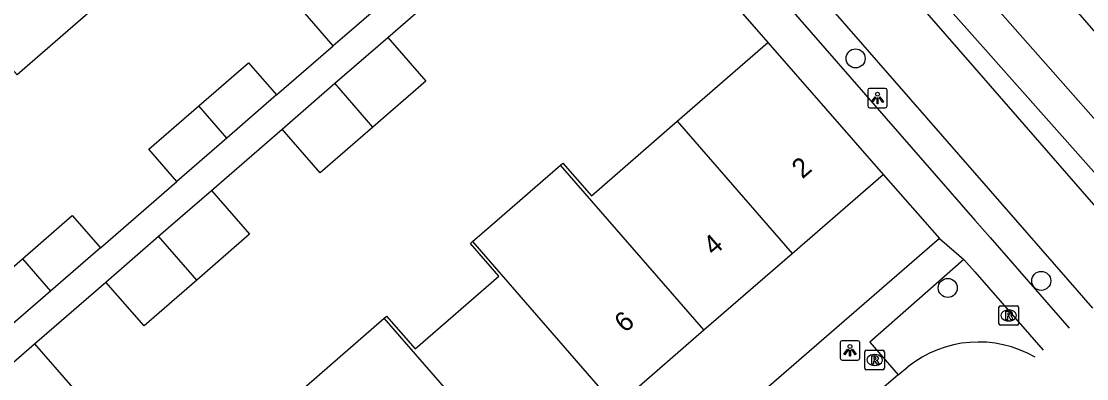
# Model space of a CAD drawing. Extents: x 155888 to 156864, y 383882 to 384671.
# Drawn here: x 156451 to 156505.7, y 384036.4 to 384054.8 of the extents above; entities that cross this region are included whole.
import ezdxf

# ---------------------------------------------------------------- set-up
doc = ezdxf.new("R2010")
doc.units = 0
for name, color, linetype in [('IMGEO_Boom', 7, 'Continuous'), ('IMGEO_Fietspad_gesloten', 7, 'Continuous'), ('IMGEO_Greppel_droge_sloot', 7, 'Continuous'), ('IMGEO_Lichtpunt', 7, 'Continuous'), ('IMGEO_Muur', 7, 'Continuous'), ('IMGEO_OVBaan_gesloten', 7, 'Continuous'), ('IMGEO_Pand', 7, 'Continuous'), ('IMGEO_Pand_nummerreeks', 7, 'Continuous'), ('IMGEO_Rijbaan_lokaal_gesloten', 7, 'Continuous'), ('IMGEO_Rioolput', 7, 'Continuous'), ('IMGEO_Voetpad_open', 7, 'Continuous')]:
    doc.layers.add(name, color=color, linetype=linetype)

msp = doc.modelspace()

# ---------------------------------------------------------------- linework, layer by layer
at = {"layer": 'IMGEO_Boom'}
for centre in [(156493.878, 384052.911), (156503.413, 384041.47), (156498.61, 384041.107)]:
    msp.add_circle(centre, 0.489, dxfattribs=at)
at = {"layer": 'IMGEO_Fietspad_gesloten'}
for points in [[(156508.758, 384042.359), (156507.724, 384043.553), (156500, 384052.421), (156466.101, 384091.342), (156424.652, 384138.668), (156398.32, 384169.108)], [(156506.058, 384040.061), (156504.79, 384041.525), (156500, 384047.025), (156463.606, 384088.814)]]:
    msp.add_lwpolyline(points, dxfattribs=at)
at = {"layer": 'IMGEO_Greppel_droge_sloot'}
msp.add_lwpolyline([(156509.636, 384043.106), (156500, 384053.967), (156494.009, 384060.719), (156471.994, 384086.237), (156471.129, 384087.831), (156471.811, 384088.508), (156473.933, 384086.903), (156495.233, 384062.187), (156500, 384056.78), (156511.018, 384044.283)], dxfattribs=at)
at = {"layer": 'IMGEO_Lichtpunt'}
for p, q in [((156494.502, 384051.273), (156494.502, 384050.466)), ((156494.502, 384051.273), (156494.502, 384050.466)), ((156495.404, 384051.368), (156494.596, 384051.368)), ((156495.404, 384051.368), (156494.596, 384051.368)), ((156495.498, 384050.466), (156495.498, 384051.273)), ((156495.498, 384050.466), (156495.498, 384051.273)), ((156494.596, 384050.372), (156495.404, 384050.372)), ((156494.596, 384050.372), (156495.404, 384050.372)), ((156493.092, 384038.297), (156493.092, 384037.49)), ((156493.092, 384038.297), (156493.092, 384037.49)), ((156493.994, 384038.392), (156493.186, 384038.392)), ((156493.994, 384038.392), (156493.186, 384038.392)), ((156494.088, 384037.49), (156494.088, 384038.297)), ((156494.088, 384037.49), (156494.088, 384038.297)), ((156493.186, 384037.396), (156493.994, 384037.396)), ((156493.186, 384037.396), (156493.994, 384037.396))]:
    msp.add_line(p, q, dxfattribs=at)
for points in [[(156494.876, 384050.937), (156494.915, 384050.909), (156494.727, 384050.647), (156494.689, 384050.674), (156494.876, 384050.937)], [(156494.978, 384050.889), (156495.025, 384050.889), (156495.025, 384050.567), (156494.978, 384050.567), (156494.978, 384050.889)], [(156495.088, 384050.909), (156495.126, 384050.936), (156495.313, 384050.674), (156495.274, 384050.646), (156495.088, 384050.909)], [(156493.466, 384037.961), (156493.505, 384037.933), (156493.317, 384037.671), (156493.279, 384037.698), (156493.466, 384037.961)], [(156493.678, 384037.933), (156493.716, 384037.96), (156493.903, 384037.698), (156493.864, 384037.67), (156493.678, 384037.933)], [(156493.568, 384037.913), (156493.615, 384037.913), (156493.615, 384037.591), (156493.568, 384037.591), (156493.568, 384037.913)]]:
    msp.add_lwpolyline(points, dxfattribs=at)
for centre in [(156495.001, 384051.071), (156493.591, 384038.095)]:
    msp.add_circle(centre, 0.0994, dxfattribs=at)
for centre, start, end in [((156494.596, 384051.273), 90, 180), ((156494.596, 384051.273), 90, 180), ((156495.404, 384051.273), 0, 90), ((156495.404, 384051.273), 0, 90), ((156494.596, 384050.466), 180, 270), ((156494.596, 384050.466), 180, 270), ((156495.404, 384050.466), 270, 0), ((156495.404, 384050.466), 270, 360), ((156493.186, 384038.297), 90, 180), ((156493.186, 384038.297), 90, 180), ((156493.994, 384038.297), 0, 90), ((156493.994, 384038.297), 0, 90), ((156493.186, 384037.49), 180, 270), ((156493.186, 384037.49), 180, 270), ((156493.994, 384037.49), 270, 0), ((156493.994, 384037.49), 270, 360)]:
    msp.add_arc(centre, 0.0946, start, end, dxfattribs=at)
at = {"layer": 'IMGEO_Muur'}
msp.add_lwpolyline([(156472.819, 384072.746), (156489.369, 384053.729)], dxfattribs=at)
at = {"layer": 'IMGEO_OVBaan_gesloten'}
msp.add_lwpolyline([(156407.083, 384168.169), (156407.746, 384167.396), (156407.842, 384167.479), (156410.66, 384164.227), (156441.975, 384128.147), (156500, 384061.368), (156513.218, 384046.155)], dxfattribs=at)
at = {"layer": 'IMGEO_Pand'}
for points in [[(156467.042, 384053.555), (156465.599, 384055.216), (156469.222, 384058.363)], [(156454.5, 384056.972), (156455.377, 384056.039), (156450.81, 384052.073), (156450.035, 384052.966)], [(156470.666, 384056.703), (156468.1, 384054.474), (156467.042, 384053.555)], [(156467.131, 384051.631), (156469.848, 384053.992)], [(156469.848, 384053.992), (156471.809, 384051.736), (156469.09, 384049.374)], [(156484.71, 384049.676), (156489.369, 384053.729)], [(156489.369, 384053.729), (156495.285, 384046.946)], [(156460.146, 384050.472), (156462.697, 384052.688), (156464.138, 384051.03)], [(156464.422, 384049.277), (156467.131, 384051.631)], [(156469.09, 384049.374), (156467.131, 384051.631)], [(156464.138, 384051.03), (156461.587, 384048.813)], [(156459.013, 384046.577), (156457.572, 384048.235), (156460.146, 384050.472)], [(156461.587, 384048.813), (156460.146, 384050.472)], [(156478.718, 384047.419), (156478.844, 384047.529), (156480.307, 384045.846), (156484.71, 384049.676)], [(156484.71, 384049.676), (156490.613, 384042.883)], [(156469.09, 384049.374), (156466.383, 384047.021), (156464.422, 384049.277)], [(156461.587, 384048.813), (156459.013, 384046.577)], [(156474.199, 384043.489), (156475.071, 384044.248), (156478.718, 384047.419)], [(156486.087, 384038.947), (156478.718, 384047.419)], [(156490.613, 384042.883), (156495.285, 384046.946)], [(156458.076, 384043.762), (156460.792, 384046.123)], [(156460.792, 384046.123), (156462.756, 384043.864), (156460.038, 384041.502)], [(156451.089, 384042.6), (156453.648, 384044.824), (156455.089, 384043.166)], [(156455.367, 384041.408), (156458.076, 384043.762)], [(156460.038, 384041.502), (156458.076, 384043.762)], [(156469.673, 384039.552), (156469.791, 384039.654), (156471.254, 384037.972), (156475.554, 384041.712), (156474.091, 384043.395), (156474.199, 384043.489)], [(156474.199, 384043.489), (156481.56, 384035.01)], [(156455.089, 384043.166), (156452.529, 384040.942)], [(156486.087, 384038.947), (156490.613, 384042.883)], [(156449.964, 384038.713), (156448.523, 384040.371), (156451.089, 384042.6)], [(156451.089, 384042.6), (156452.529, 384040.942)], [(156460.038, 384041.502), (156457.331, 384039.149), (156455.367, 384041.408)], [(156452.529, 384040.942), (156449.964, 384038.713)], [(156465.147, 384035.616), (156469.673, 384039.552)], [(156477.034, 384031.074), (156469.673, 384039.552)], [(156481.56, 384035.01), (156486.087, 384038.947)], [(156449.006, 384035.881), (156451.707, 384038.228)], [(156451.707, 384038.228), (156453.668, 384035.971), (156450.967, 384033.625)]]:
    msp.add_lwpolyline(points, dxfattribs=at)
at = {"layer": 'IMGEO_Rijbaan_lokaal_gesloten'}
for points in [[(156496.069, 384036.641), (156496.558, 384037.04)], [(156496.069, 384036.641), (156493.619, 384034.523), (156493.397, 384034.33)]]:
    msp.add_lwpolyline(points, dxfattribs=at)
msp.add_arc((156500.195, 384032.533), 5.791, 59.8887, 128.9038, dxfattribs=at)
at = {"layer": 'IMGEO_Rioolput'}
for p, q in [((156501.317, 384040.19), (156502.169, 384040.19)), ((156501.242, 384039.264), (156501.242, 384040.116)), ((156501.73, 384039.97), (156501.755, 384039.97)), ((156502.243, 384040.116), (156502.243, 384039.264)), ((156502.169, 384039.19), (156501.317, 384039.19)), ((156501.753, 384039.41), (156501.728, 384039.41)), ((156494.354, 384036.975), (156494.354, 384037.827)), ((156494.429, 384037.901), (156495.281, 384037.901)), ((156494.842, 384037.681), (156494.867, 384037.681)), ((156495.355, 384037.827), (156495.355, 384036.975)), ((156495.281, 384036.901), (156494.429, 384036.901)), ((156494.865, 384037.121), (156494.84, 384037.121))]:
    msp.add_line(p, q, dxfattribs=at)
for points in [[(156501.317, 384040.19), (156502.169, 384040.19)], [(156501.242, 384039.264), (156501.242, 384040.116)], [(156501.831, 384039.888), (156501.579, 384039.89), (156501.579, 384039.49)], [(156501.579, 384039.49), (156501.703, 384039.49), (156501.703, 384039.652), (156501.714, 384039.652)], [(156501.757, 384039.809), (156501.703, 384039.809), (156501.703, 384039.728)], [(156501.703, 384039.728), (156501.755, 384039.728)], [(156501.761, 384039.623), (156501.832, 384039.49), (156501.972, 384039.49), (156501.907, 384039.616)], [(156502.243, 384040.116), (156502.243, 384039.264)], [(156502.169, 384039.19), (156501.317, 384039.19)], [(156494.354, 384036.975), (156494.354, 384037.827)], [(156494.429, 384037.901), (156495.281, 384037.901)], [(156494.943, 384037.599), (156494.691, 384037.601), (156494.691, 384037.201)], [(156494.869, 384037.52), (156494.815, 384037.52), (156494.815, 384037.439)], [(156494.815, 384037.439), (156494.867, 384037.439)], [(156495.355, 384037.827), (156495.355, 384036.975)], [(156495.281, 384036.901), (156494.429, 384036.901)], [(156494.691, 384037.201), (156494.815, 384037.201), (156494.815, 384037.363), (156494.826, 384037.363)], [(156494.873, 384037.334), (156494.944, 384037.201), (156495.084, 384037.201), (156495.019, 384037.327)]]:
    msp.add_lwpolyline(points, dxfattribs=at)
for centre, radius, start, end in [((156501.319, 384040.114), 0.0765, 91.552, 178.448), ((156501.319, 384040.114), 0.0765, 91.552, 178.448), ((156502.167, 384040.114), 0.0765, 1.552, 88.448), ((156502.167, 384040.114), 0.0765, 1.552, 88.448), ((156501.713, 384039.599), 0.0533, 26.0293, 88.6989), ((156501.739, 384039.917), 0.19, 274.7715, 282.9687), ((156501.763, 384039.713), 0.0964, 77.0061, 93.1865), ((156501.777, 384039.77), 0.0378, 276.6634, 79.6772), ((156501.83, 384039.778), 0.109, 350.3612, 89.416), ((156501.828, 384039.778), 0.112, 277.5842, 350.9817), ((156501.812, 384039.563), 0.108, 29.5134, 73.7905), ((156501.319, 384039.266), 0.0765, 181.552, 268.448), ((156501.319, 384039.266), 0.0765, 181.552, 268.448), ((156502.167, 384039.266), 0.0765, 271.552, 358.448), ((156502.167, 384039.266), 0.0765, 271.552, 358.448), ((156494.431, 384037.825), 0.0765, 91.552, 178.448), ((156494.431, 384037.825), 0.0765, 91.552, 178.448), ((156494.851, 384037.628), 0.19, 274.7715, 282.9687), ((156494.875, 384037.424), 0.0964, 77.0061, 93.1865), ((156494.889, 384037.481), 0.0378, 276.6634, 79.6772), ((156494.942, 384037.489), 0.109, 350.3612, 89.416), ((156494.94, 384037.489), 0.112, 277.5842, 350.9817), ((156495.279, 384037.825), 0.0765, 1.552, 88.448), ((156495.279, 384037.825), 0.0765, 1.552, 88.448), ((156494.431, 384036.977), 0.0765, 181.552, 268.448), ((156494.431, 384036.977), 0.0765, 181.552, 268.448), ((156494.825, 384037.31), 0.0533, 26.0293, 88.6989), ((156494.924, 384037.274), 0.108, 29.5134, 73.7905), ((156495.279, 384036.977), 0.0765, 271.552, 358.448), ((156495.279, 384036.977), 0.0765, 271.552, 358.448)]:
    msp.add_arc(centre, radius, start, end, dxfattribs=at)
for centre, major_axis, ratio, start_param, end_param in [((156501.729, 384039.69), (-0.387, 0.002), 0.722429, 4.712389, 7.853982), ((156501.754, 384039.69), (-0.39, 0.002), 0.717154, 1.570796, 4.712389), ((156494.841, 384037.401), (-0.387, 0.002), 0.722429, 4.712389, 7.853982), ((156494.866, 384037.401), (-0.39, 0.002), 0.717154, 1.570796, 4.712389)]:
    msp.add_ellipse(centre, major_axis=major_axis, ratio=ratio, start_param=start_param, end_param=end_param, dxfattribs=at)
at = {"layer": 'IMGEO_Voetpad_open'}
for points in [[(156460.775, 384089.642), (156500, 384044.592), (156500.782, 384043.694), (156504.85, 384039.032)], [(156480.831, 384063.539), (156489.369, 384053.729)], [(156469.848, 384053.992), (156473.485, 384057.153)], [(156464.138, 384051.03), (156467.042, 384053.555)], [(156460.792, 384046.123), (156464.422, 384049.277)], [(156495.285, 384046.946), (156498.182, 384043.649)], [(156455.089, 384043.166), (156459.013, 384046.577)], [(156498.182, 384043.649), (156452.547, 384004.012)], [(156498.182, 384043.649), (156499.442, 384042.575)], [(156499.442, 384042.575), (156494.617, 384038.319), (156496.069, 384036.641)], [(156499.442, 384042.575), (156500, 384041.935), (156503.519, 384037.899)], [(156451.707, 384038.228), (156455.367, 384041.408)]]:
    msp.add_lwpolyline(points, dxfattribs=at)

# ---------------------------------------------------------------- texts
at = {"layer": 'IMGEO_Pand_nummerreeks'}
for s, p in [('2', (156491.145, 384046.684)), ('4', (156486.589, 384042.723)), ('6', (156482.032, 384038.76))]:
    msp.add_text(s, height=1, rotation=41.0123, dxfattribs=at).set_placement(p)

doc.saveas('drawing.dxf')
